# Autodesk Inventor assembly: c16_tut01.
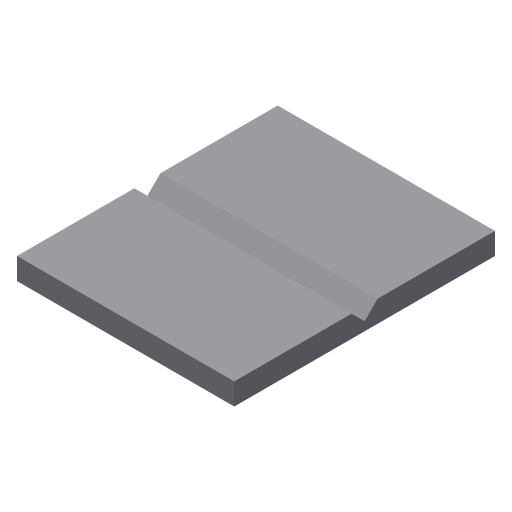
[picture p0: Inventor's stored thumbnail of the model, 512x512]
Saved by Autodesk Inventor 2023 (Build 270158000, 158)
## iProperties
Created: 2010-05
Part Number: c16_tut01.
Document SubType Name: Weldment
Designer: CADSoft
Weld Material: Welded Aluminum-6061
Author: CADSoft
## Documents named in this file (2)
- D:\PROJECTS\Project 2022\Autodesk Inventor For Professional 2023\RESOURCES INVENTOR 2023\RESOURCES INVENTOR 2023\Inventor_2023_tut\Inventor_2023_tut\c16_Inv_2023_tut\c16_Inv_tut_2022\c16_tut01\c16_tut01..iam
- D:\PROJECTS\Project 2022\Autodesk Inventor For Professional 2023\RESOURCES INVENTOR 2023\RESOURCES INVENTOR 2023\Inventor_2023_tut\Inventor_2023_tut\c16_Inv_2023_tut\c16_Inv_tut_2022\c16_tut01\Plate..ipt
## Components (2 placed, 1 different names)
1. Plate.:1 — Mate:1, Flush:1, Flush:2
2. Plate.:2 — Mate:1, Flush:1, Flush:2
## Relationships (3: Flush 2, Mate 1)
- Mate:1: Plate.:1 ↔ Plate.:2
- Flush:1: Plate.:1 ↔ Plate.:2
- Flush:2: Plate.:1 ↔ Plate.:2
